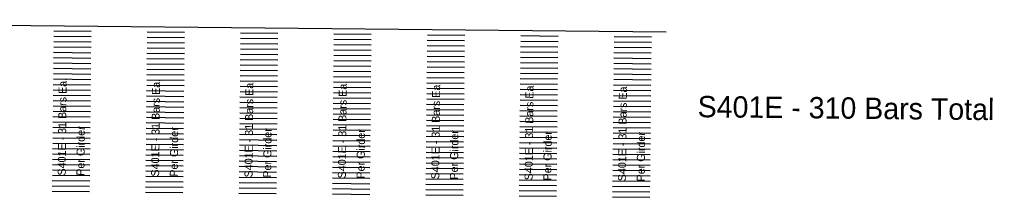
# Model space of a CAD drawing. Extents: x 632547 to 633311, y 380830 to 386139.
# Drawn here: x 633157.1 to 633248.3, y 381403.9 to 381420.6 of the extents above; entities that cross this region are included whole.
import ezdxf

# ---------------------------------------------------------------- set-up
doc = ezdxf.new("R2010")
doc.units = 0
for name, color, linetype in [('B_Border', 7, 'Continuous'), ('R_Border_Scale', 7, 'Continuous'), ('R_Wall', 7, 'Continuous')]:
    doc.layers.add(name, color=color, linetype=linetype)

msp = doc.modelspace()

# ---------------------------------------------------------------- linework, layer by layer
at = {"layer": 'B_Border'}
msp.add_line((633217.685, 381419.389), (633100.631, 381420.573), dxfattribs=at)
at = {"layer": 'R_Border_Scale'}
for p, q in [((633163.808, 381419.434), (633160.308, 381419.469)), ((633172.557, 381419.345), (633169.058, 381419.38)), ((633181.307, 381419.257), (633177.807, 381419.292)), ((633163.798, 381418.434), (633160.298, 381418.469)), ((633163.803, 381418.934), (633160.303, 381418.969)), ((633172.547, 381418.345), (633169.047, 381418.381)), ((633172.552, 381418.845), (633169.053, 381418.88)), ((633181.302, 381418.757), (633177.802, 381418.792)), ((633190.051, 381418.668), (633186.552, 381418.703)), ((633190.057, 381419.168), (633186.557, 381419.203)), ((633198.801, 381418.58), (633195.301, 381418.615)), ((633198.806, 381419.08), (633195.306, 381419.115)), ((633207.551, 381418.491), (633204.051, 381418.526)), ((633207.556, 381418.991), (633204.056, 381419.026)), ((633216.3, 381418.402), (633212.8, 381418.438)), ((633216.305, 381418.902), (633212.805, 381418.938)), ((633163.788, 381417.434), (633160.288, 381417.469)), ((633163.793, 381417.934), (633160.293, 381417.969)), ((633172.542, 381417.845), (633169.042, 381417.881)), ((633181.292, 381417.757), (633177.792, 381417.792)), ((633181.297, 381418.257), (633177.797, 381418.292)), ((633190.041, 381417.668), (633186.542, 381417.704)), ((633190.046, 381418.168), (633186.547, 381418.203)), ((633198.791, 381417.58), (633195.291, 381417.615)), ((633198.796, 381418.08), (633195.296, 381418.115)), ((633207.54, 381417.491), (633204.041, 381417.526)), ((633207.546, 381417.991), (633204.046, 381418.026)), ((633216.29, 381417.403), (633212.79, 381417.438)), ((633216.295, 381417.903), (633212.795, 381417.938)), ((633163.783, 381416.934), (633160.283, 381416.969)), ((633172.532, 381416.845), (633169.032, 381416.881)), ((633172.537, 381417.345), (633169.037, 381417.381)), ((633181.282, 381416.757), (633177.782, 381416.792)), ((633181.287, 381417.257), (633177.787, 381417.292)), ((633190.031, 381416.668), (633186.531, 381416.704)), ((633190.036, 381417.168), (633186.536, 381417.204)), ((633198.781, 381416.58), (633195.281, 381416.615)), ((633198.786, 381417.08), (633195.286, 381417.115)), ((633207.53, 381416.491), (633204.031, 381416.527)), ((633207.535, 381416.991), (633204.036, 381417.026)), ((633216.285, 381416.903), (633212.785, 381416.938)), ((633163.772, 381415.934), (633160.273, 381415.969)), ((633163.778, 381416.434), (633160.278, 381416.469)), ((633172.522, 381415.845), (633169.022, 381415.881)), ((633172.527, 381416.345), (633169.027, 381416.381)), ((633181.272, 381415.757), (633177.772, 381415.792)), ((633181.277, 381416.257), (633177.777, 381416.292)), ((633190.021, 381415.668), (633186.521, 381415.704)), ((633190.026, 381416.168), (633186.526, 381416.204)), ((633198.771, 381415.58), (633195.271, 381415.615)), ((633198.776, 381416.08), (633195.276, 381416.115)), ((633207.525, 381415.991), (633204.025, 381416.027)), ((633216.275, 381415.903), (633212.775, 381415.938)), ((633216.28, 381416.403), (633212.78, 381416.438)), ((633163.762, 381414.934), (633160.263, 381414.969)), ((633163.767, 381415.434), (633160.268, 381415.469)), ((633172.512, 381414.845), (633169.012, 381414.881)), ((633172.517, 381415.345), (633169.017, 381415.381)), ((633181.261, 381414.757), (633177.762, 381414.792)), ((633181.267, 381415.257), (633177.767, 381415.292)), ((633190.011, 381414.668), (633186.511, 381414.704)), ((633190.016, 381415.168), (633186.516, 381415.204)), ((633198.766, 381415.08), (633195.266, 381415.115)), ((633207.515, 381414.991), (633204.015, 381415.027)), ((633207.52, 381415.491), (633204.02, 381415.527)), ((633216.265, 381414.903), (633212.765, 381414.938)), ((633216.27, 381415.403), (633212.77, 381415.438)), ((633163.752, 381413.934), (633160.252, 381413.969)), ((633163.757, 381414.434), (633160.257, 381414.469)), ((633172.502, 381413.845), (633169.002, 381413.881)), ((633172.507, 381414.345), (633169.007, 381414.381)), ((633181.251, 381413.757), (633177.752, 381413.792)), ((633181.256, 381414.257), (633177.757, 381414.292)), ((633190.006, 381414.168), (633186.506, 381414.204)), ((633198.756, 381414.08), (633195.256, 381414.115)), ((633198.761, 381414.58), (633195.261, 381414.615)), ((633207.505, 381413.991), (633204.005, 381414.027)), ((633207.51, 381414.491), (633204.01, 381414.527)), ((633216.255, 381413.903), (633212.755, 381413.938)), ((633216.26, 381414.403), (633212.76, 381414.438)), ((633163.742, 381412.934), (633160.242, 381412.969)), ((633163.747, 381413.434), (633160.247, 381413.469)), ((633172.492, 381412.845), (633168.992, 381412.881)), ((633172.497, 381413.345), (633168.997, 381413.381)), ((633181.246, 381413.257), (633177.746, 381413.292)), ((633189.996, 381413.168), (633186.496, 381413.204)), ((633190.001, 381413.668), (633186.501, 381413.704)), ((633198.745, 381413.08), (633195.246, 381413.115)), ((633198.75, 381413.58), (633195.251, 381413.615)), ((633207.495, 381412.991), (633203.995, 381413.027)), ((633207.5, 381413.491), (633204, 381413.527)), ((633216.244, 381412.903), (633212.745, 381412.938)), ((633216.25, 381413.403), (633212.75, 381413.438)), ((633163.732, 381411.934), (633160.232, 381411.969)), ((633163.737, 381412.434), (633160.237, 381412.469)), ((633172.487, 381412.345), (633168.987, 381412.381)), ((633181.236, 381412.257), (633177.736, 381412.292)), ((633181.241, 381412.757), (633177.741, 381412.792)), ((633189.986, 381412.168), (633186.486, 381412.204)), ((633189.991, 381412.668), (633186.491, 381412.704)), ((633198.735, 381412.08), (633195.235, 381412.115)), ((633198.74, 381412.58), (633195.241, 381412.615)), ((633207.485, 381411.991), (633203.985, 381412.027)), ((633207.49, 381412.491), (633203.99, 381412.527)), ((633216.239, 381412.403), (633212.74, 381412.438)), ((633163.727, 381411.434), (633160.227, 381411.469)), ((633172.477, 381411.345), (633168.977, 381411.381)), ((633172.482, 381411.845), (633168.982, 381411.881)), ((633181.226, 381411.257), (633177.726, 381411.292)), ((633181.231, 381411.757), (633177.731, 381411.792)), ((633189.976, 381411.168), (633186.476, 381411.204)), ((633189.981, 381411.668), (633186.481, 381411.704)), ((633198.725, 381411.08), (633195.225, 381411.115)), ((633198.73, 381411.58), (633195.23, 381411.615)), ((633207.48, 381411.491), (633203.98, 381411.527)), ((633216.229, 381411.403), (633212.73, 381411.438)), ((633216.234, 381411.903), (633212.735, 381411.938)), ((633163.717, 381410.434), (633160.217, 381410.469)), ((633163.722, 381410.934), (633160.222, 381410.969)), ((633172.466, 381410.346), (633168.967, 381410.381)), ((633172.471, 381410.846), (633168.972, 381410.881)), ((633181.216, 381410.257), (633177.716, 381410.292)), ((633181.221, 381410.757), (633177.721, 381410.792)), ((633189.965, 381410.168), (633186.466, 381410.204)), ((633189.971, 381410.668), (633186.471, 381410.704)), ((633198.72, 381410.58), (633195.22, 381410.615)), ((633207.47, 381410.491), (633203.97, 381410.527)), ((633207.475, 381410.991), (633203.975, 381411.027)), ((633216.219, 381410.403), (633212.719, 381410.438)), ((633216.224, 381410.903), (633212.724, 381410.938)), ((633163.707, 381409.434), (633160.207, 381409.47)), ((633163.712, 381409.934), (633160.212, 381409.969)), ((633172.456, 381409.346), (633168.956, 381409.381)), ((633172.461, 381409.846), (633168.962, 381409.881)), ((633181.206, 381409.257), (633177.706, 381409.292)), ((633181.211, 381409.757), (633177.711, 381409.792)), ((633189.96, 381409.669), (633186.461, 381409.704)), ((633198.71, 381409.58), (633195.21, 381409.615)), ((633198.715, 381410.08), (633195.215, 381410.115)), ((633207.46, 381409.491), (633203.96, 381409.527)), ((633207.465, 381409.991), (633203.965, 381410.027)), ((633216.209, 381409.403), (633212.709, 381409.438)), ((633216.214, 381409.903), (633212.714, 381409.938)), ((633163.697, 381408.434), (633160.197, 381408.47)), ((633163.702, 381408.934), (633160.202, 381408.97)), ((633172.446, 381408.346), (633168.946, 381408.381)), ((633172.451, 381408.846), (633168.951, 381408.881)), ((633181.201, 381408.757), (633177.701, 381408.792)), ((633189.95, 381408.669), (633186.45, 381408.704)), ((633189.955, 381409.169), (633186.456, 381409.204)), ((633198.7, 381408.58), (633195.2, 381408.615)), ((633198.705, 381409.08), (633195.205, 381409.115)), ((633207.449, 381408.492), (633203.95, 381408.527)), ((633207.454, 381408.991), (633203.955, 381409.027)), ((633216.199, 381408.403), (633212.699, 381408.438)), ((633216.204, 381408.903), (633212.704, 381408.938)), ((633163.686, 381407.434), (633160.187, 381407.47)), ((633163.692, 381407.934), (633160.192, 381407.97)), ((633172.441, 381407.846), (633168.941, 381407.881)), ((633181.191, 381407.757), (633177.691, 381407.793)), ((633181.196, 381408.257), (633177.696, 381408.293)), ((633189.94, 381407.669), (633186.44, 381407.704)), ((633189.945, 381408.169), (633186.445, 381408.204)), ((633198.69, 381407.58), (633195.19, 381407.616)), ((633198.695, 381408.08), (633195.195, 381408.115)), ((633207.439, 381407.492), (633203.939, 381407.527)), ((633207.444, 381407.992), (633203.945, 381408.027)), ((633216.189, 381407.403), (633212.689, 381407.438)), ((633216.194, 381407.903), (633212.694, 381407.938)), ((633163.681, 381406.934), (633160.182, 381406.97)), ((633172.431, 381406.846), (633168.931, 381406.881)), ((633172.436, 381407.346), (633168.936, 381407.381)), ((633181.181, 381406.757), (633177.681, 381406.793)), ((633181.186, 381407.257), (633177.686, 381407.293)), ((633189.93, 381406.669), (633186.43, 381406.704)), ((633189.935, 381407.169), (633186.435, 381407.204)), ((633198.68, 381406.58), (633195.18, 381406.616)), ((633198.685, 381407.08), (633195.185, 381407.116)), ((633207.429, 381406.492), (633203.929, 381406.527)), ((633207.434, 381406.992), (633203.934, 381407.027)), ((633216.184, 381406.903), (633212.684, 381406.938)), ((633163.671, 381405.934), (633160.171, 381405.97)), ((633163.676, 381406.434), (633160.177, 381406.47)), ((633172.421, 381405.846), (633168.921, 381405.881)), ((633172.426, 381406.346), (633168.926, 381406.381)), ((633181.17, 381405.757), (633177.671, 381405.793)), ((633181.175, 381406.257), (633177.676, 381406.293)), ((633189.92, 381405.669), (633186.42, 381405.704)), ((633189.925, 381406.169), (633186.425, 381406.204)), ((633198.67, 381405.58), (633195.17, 381405.616)), ((633198.675, 381406.08), (633195.175, 381406.116)), ((633207.424, 381405.992), (633203.924, 381406.027)), ((633216.174, 381405.903), (633212.674, 381405.939)), ((633216.179, 381406.403), (633212.679, 381406.439)), ((633163.661, 381404.934), (633160.161, 381404.97)), ((633163.666, 381405.434), (633160.166, 381405.47)), ((633172.411, 381404.846), (633168.911, 381404.881)), ((633172.416, 381405.346), (633168.916, 381405.381)), ((633181.16, 381404.757), (633177.66, 381404.793)), ((633181.165, 381405.257), (633177.666, 381405.293)), ((633189.91, 381404.669), (633186.41, 381404.704)), ((633189.915, 381405.169), (633186.415, 381405.204)), ((633198.664, 381405.08), (633195.165, 381405.116)), ((633207.414, 381404.992), (633203.914, 381405.027)), ((633207.419, 381405.492), (633203.919, 381405.527)), ((633216.164, 381404.903), (633212.664, 381404.939)), ((633216.169, 381405.403), (633212.669, 381405.439)), ((633163.656, 381404.434), (633160.156, 381404.47)), ((633172.406, 381404.346), (633168.906, 381404.381)), ((633181.155, 381404.257), (633177.655, 381404.293)), ((633189.905, 381404.169), (633186.405, 381404.204)), ((633198.654, 381404.08), (633195.155, 381404.116)), ((633198.659, 381404.58), (633195.16, 381404.616)), ((633207.404, 381403.992), (633203.904, 381404.027)), ((633207.409, 381404.492), (633203.909, 381404.527)), ((633216.153, 381403.903), (633212.654, 381403.939)), ((633216.159, 381404.403), (633212.659, 381404.439))]:
    msp.add_line(p, q, dxfattribs=at)

# ---------------------------------------------------------------- texts
at = {"layer": 'R_Wall'}
for s, height, rotation, p in [('S401E - 31 Bars Ea,', 0.75, 89.43036, (633161.421, 381405.957)), ('S401E - 31 Bars Ea,', 0.75, 89.43036, (633170.171, 381405.868)), ('S401E - 31 Bars Ea,', 0.75, 89.43036, (633178.921, 381405.78)), ('S401E - 31 Bars Ea,', 0.75, 89.43036, (633187.67, 381405.691)), ('S401E - 31 Bars Ea,', 0.75, 89.43036, (633196.42, 381405.603)), ('S401E - 31 Bars Ea,', 0.75, 89.43036, (633205.169, 381405.514)), ('S401E - 31 Bars Ea,', 0.75, 89.43036, (633213.919, 381405.426)), ('S401E - 310 Bars Total', 2, 359.43036, (633220.623, 381411.422)), ('Per Girder', 0.75, 89.43036, (633163.171, 381405.94)), ('Per Girder', 0.75, 89.43036, (633171.921, 381405.851)), ('Per Girder', 0.75, 89.43036, (633180.67, 381405.763)), ('Per Girder', 0.75, 89.43036, (633189.42, 381405.674)), ('Per Girder', 0.75, 89.43036, (633198.17, 381405.585)), ('Per Girder', 0.75, 89.43036, (633206.919, 381405.497)), ('Per Girder', 0.75, 89.43036, (633215.669, 381405.408))]:
    msp.add_text(s, height=height, rotation=rotation, dxfattribs=at).set_placement(p)

doc.saveas('drawing.dxf')
